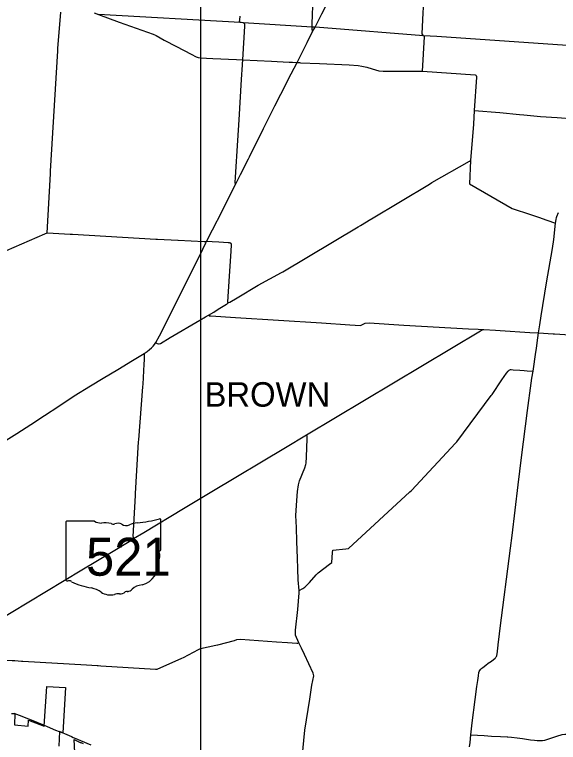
# Model space of a CAD drawing. Extents: x 1729596 to 1925846, y 659247 to 911751.
# Drawn here: x 1821771 to 1841732, y 833985 to 860705 of the extents above; entities that cross this region are included whole.
import ezdxf

# ---------------------------------------------------------------- set-up
doc = ezdxf.new("R2010")
doc.units = 0
for name, color, linetype in [('GM_X_Corporation', 7, 'Continuous'), ('GM_X_County_Road', 7, 'Continuous'), ('GM_X_State_Route', 7, 'Continuous'), ('GM_X_State_Shield', 7, 'Continuous'), ('GM_X_Township', 7, 'Continuous'), ('GM_X_Township_Road', 7, 'Continuous'), ('GM_X_Township_Text', 7, 'Continuous'), ('GM_X_US_Route', 7, 'Continuous'), ('SH_Data', 7, 'Continuous')]:
    doc.layers.add(name, color=color, linetype=linetype)

msp = doc.modelspace()

# ---------------------------------------------------------------- linework, layer by layer
at = {"layer": 'GM_X_Corporation'}
for points in [[(1821656, 835046), (1821781, 835050), (1821769, 834633), (1822268, 834587), (1822281, 834808), (1822854, 834577), (1822956, 836039), (1823645, 836005), (1823540, 834336), (1823415, 834383), (1823397, 833851)], [(1824058, 832202), (1823955, 834094), (1824182, 833983), (1824200, 833986), (1824290, 833942)]]:
    msp.add_lwpolyline(points, dxfattribs=at)
at = {"layer": 'GM_X_County_Road'}
for points in [[(1824699, 860768), (1824857, 860710), (1825612, 860430), (1826656, 860059), (1826853, 859982), (1826971, 859934), (1827258, 859768), (1827710, 859527), (1828254, 859247), (1828432, 859153), (1828513, 859123), (1828584, 859112), (1829052, 859088), (1829917, 859051), (1830145, 859048), (1831204, 858991), (1831412, 858982), (1831846, 858956), (1831978, 858953), (1832140, 858950)], [(1832140, 858950), (1832225, 858943), (1832265, 858939), (1832961, 858909), (1834057, 858860), (1834388, 858837), (1834514, 858807), (1834697, 858768), (1834897, 858714), (1835014, 858675), (1835136, 858637), (1835294, 858625), (1835692, 858625), (1836196, 858623), (1836448, 858626), (1836739, 858621)], [(1836739, 858621), (1838675, 858491), (1838704, 858476), (1838715, 858460)], [(1838715, 858460), (1838725, 858446), (1838731, 858409), (1838644, 857189), (1838612, 856680), (1838509, 855352), (1838468, 854485), (1840033, 853588), (1840704, 853369), (1840998, 853268), (1841304, 853162), (1841625, 853051)], [(1841006, 849018), (1841051, 849314), (1841101, 849645), (1841295, 850857), (1841512, 852119), (1841560, 852444), (1841625, 853051), (1841645, 853178), (1841666, 853257), (1841678, 853296), (1841734, 853436)], [(1827483, 848845), (1828569, 849486), (1828773, 849606), (1828890, 849668)], [(1828890, 849668), (1828890, 849668), (1828924, 849648), (1828977, 849643), (1829879, 849585), (1833037, 849389), (1834076, 849311), (1834469, 849288), (1834642, 849380), (1834781, 849392), (1836063, 849299), (1838431, 849174), (1838783, 849153), (1838998, 849141)], [(1838466, 833825), (1838487, 833985), (1838519, 834265), (1838567, 834705), (1838674, 835560), (1838743, 836040), (1838773, 836253), (1838796, 836429), (1838814, 836551), (1838826, 836590), (1838844, 836629), (1838867, 836664), (1838885, 836685), (1838954, 836740), (1839072, 836824), (1839157, 836890), (1839273, 836974), (1839413, 837081), (1839426, 837095), (1839438, 837110), (1839458, 837143), (1839466, 837161), (1839472, 837179), (1839477, 837198), (1839478, 837221), (1839510, 837440), (1839538, 837684), (1839547, 837760), (1839596, 838176), (1839967, 841111), (1840035, 841581), (1840259, 843439), (1840381, 844450), (1840596, 846166), (1840736, 847171), (1840762, 847354), (1840807, 847615), (1840906, 848311), (1840922, 848444), (1840955, 848656), (1841006, 849018)], [(1826954, 848664), (1826976, 848639), (1827002, 848628), (1827054, 848615), (1827084, 848617), (1827126, 848635), (1827483, 848845)], [(1824834, 836804), (1824939, 836797), (1826941, 836673), (1827000, 836670), (1827915, 837079), (1827969, 837103), (1828528, 837401), (1828591, 837434), (1829159, 837555), (1829234, 837570), (1829847, 837731), (1829932, 837765), (1830068, 837770), (1831380, 837679), (1831789, 837651), (1832132, 837627), (1832164, 837633), (1832207, 837647), (1832086, 837925), (1832077, 837968), (1832081, 838107), (1832167, 838864), (1832211, 839479), (1832217, 839559), (1832354, 839640), (1832420, 839679), (1832530, 839793), (1832596, 839862), (1832843, 840137), (1832910, 840211), (1833329, 840531), (1833411, 840594), (1833446, 840962), (1833453, 841041), (1833926, 841092), (1834029, 841103), (1836280, 843180), (1836334, 843229), (1837952, 844970), (1838003, 845024), (1839263, 846719), (1839296, 846763), (1839657, 847296), (1839829, 847544), (1839890, 847618), (1839921, 847646), (1839949, 847661), (1839978, 847670), (1839994, 847672), (1840065, 847668), (1840312, 847648), (1840471, 847640), (1840580, 847631), (1840807, 847615)], [(1820825, 837049), (1820913, 837042), (1821680, 836994), (1821777, 836987), (1822028, 836972), (1822074, 836969)], [(1822074, 836969), (1824417, 836829)], [(1824417, 836829), (1824803, 836806), (1824834, 836804), (1824834, 836804)]]:
    msp.add_lwpolyline(points, dxfattribs=at)
at = {"layer": 'GM_X_State_Route'}
for points in [[(1824240, 840319), (1825270, 840939), (1826096, 841440), (1826142, 841474), (1826514, 841694), (1827976, 842576), (1829017, 843200), (1831719, 844816), (1832490, 845282), (1838868, 849097), (1838914, 849121), (1838998, 849141), (1839418, 849116)], [(1839418, 849116), (1839597, 849106), (1840678, 849037), (1841006, 849018)], [(1841006, 849018), (1841537, 848985), (1841586, 848982)], [(1841586, 848982), (1842167, 848948), (1842431, 848928)], [(1820468, 838053), (1820655, 838166), (1821648, 838759), (1824240, 840319)]]:
    msp.add_lwpolyline(points, dxfattribs=at)
at = {"layer": 'GM_X_State_Shield'}
for p, q in [((1823657, 842070), (1823657, 839957)), ((1823657, 842070), (1823657, 839957)), ((1824710, 842107), (1823691, 842107)), ((1824710, 842107), (1823691, 842107)), ((1827137, 841053), (1827137, 842159)), ((1827137, 841053), (1827137, 842159)), ((1827137, 841054), (1827137, 841053)), ((1827137, 841054), (1827137, 841053))]:
    msp.add_line(p, q, dxfattribs=at)
for centre, major_axis, start_param, end_param in [((1823697, 842075), (40.3, 0), 1.712693, 3.28349), ((1823697, 842075), (40.3, 0), 1.712693, 3.28349), ((1824953, 842352), (391, 0), 4.042523, 4.731795), ((1824953, 842352), (391, 0), 4.042523, 4.731795), ((1825083, 840920), (1404, 0), 1.404758, 1.657858), ((1825083, 840920), (1404, 0), 1.404758, 1.657858), ((1825402, 842086), (113, 0), 3.836095, 5.185415), ((1825402, 842086), (113, 0), 3.836095, 5.185415), ((1825567, 841841), (235, 0), 0.950623, 2.079405), ((1825567, 841841), (235, 0), 0.950623, 2.079405), ((1825870, 842176), (282, 0), 4.081561, 5.145723), ((1825870, 842176), (282, 0), 4.081561, 5.145723), ((1826368, 841461), (743, 0), 1.699011, 2.107814), ((1826368, 841461), (743, 0), 1.699011, 2.107814), ((1825898, 844988), (3691, 0), 4.814394, 5.042369), ((1825898, 844988), (3691, 0), 4.814394, 5.042369), ((1827099, 842163), (38.7, 0), 6.141152, 7.989035), ((1827099, 842163), (38.7, 0), 6.141152, 7.989035), ((1827128, 840972), (60, 0), 1.883978, 3.671073), ((1827128, 840972), (60, 0), 1.883978, 3.671073), ((1826747, 840833), (360, 0), 5.934695, 6.695948), ((1826747, 840833), (360, 0), 5.934695, 6.695948), ((1827096, 841049), (41.5, 0), 5.05454, 6.418171), ((1827096, 841049), (41.5, 0), 5.05454, 6.418171), ((1827276, 840591), (262, 0), 2.387724, 3.262537), ((1827276, 840591), (262, 0), 2.387724, 3.262537), ((1826104, 840450), (923, 0), 5.101752, 6.440018), ((1826104, 840450), (923, 0), 5.101752, 6.440018), ((1823697, 839952), (40.7, 0), 3.00124, 4.508301), ((1823697, 839952), (40.7, 0), 3.00124, 4.508301), ((1823703, 840168), (310, 0), 4.665946, 4.897461), ((1823703, 840168), (310, 0), 4.665946, 4.897461), ((1823767, 839835), (112, 0), 0.519207, 1.627899), ((1823767, 839835), (112, 0), 0.519207, 1.627899), ((1825180, 841734), (2665, 0), 4.195997, 4.488961), ((1825180, 841734), (2665, 0), 4.195997, 4.488961), ((1824385, 839008), (834, 0), 0.823519, 1.323587), ((1824385, 839008), (834, 0), 0.823519, 1.323587), ((1825853, 839752), (298, 0), 4.937069, 5.64225), ((1825853, 839752), (298, 0), 4.937069, 5.64225), ((1826494, 839364), (506, 0), 1.647645, 2.488434), ((1826494, 839364), (506, 0), 1.647645, 2.488434), ((1825287, 839824), (529, 0), 4.026481, 4.996735), ((1825287, 839824), (529, 0), 4.026481, 4.996735), ((1825593, 839094), (435, 0), 1.495662, 1.94098), ((1825593, 839094), (435, 0), 1.495662, 1.94098), ((1825632, 839666), (282, 0), 4.691044, 5.507374), ((1825632, 839666), (282, 0), 4.691044, 5.507374), ((1825887, 839462), (79.4, 0), 1.147584, 2.315152), ((1825887, 839462), (79.4, 0), 1.147584, 2.315152)]:
    msp.add_ellipse(centre, major_axis=major_axis, ratio=0.8, start_param=start_param, end_param=end_param, dxfattribs=at)
at = {"layer": 'GM_X_Township'}
msp.add_lwpolyline([(1848864, 860810), (1848787, 859601), (1848752, 859146), (1848243, 859177), (1843111, 859493), (1837275, 859897), (1836785, 859928), (1833125, 860220), (1832799, 860239), (1832694, 860243), (1830166, 860402), (1830089, 860410), (1830057, 860416), (1824857, 860710)], dxfattribs=at)
at = {"layer": 'GM_X_Township_Road'}
for points in [[(1832712, 860086), (1832692, 860180), (1832694, 860243), (1832711, 860815), (1832717, 860894), (1832916, 864638), (1832920, 864735), (1833003, 866422), (1833008, 866525), (1833111, 868476), (1833115, 868570)], [(1836801, 859906), (1836785, 859928), (1836730, 860003), (1836772, 860771), (1836832, 861759), (1836900, 861806), (1837774, 861777), (1841815, 864609), (1841870, 865582)], [(1822973, 852697), (1823090, 854855), (1823095, 854950), (1823360, 859378), (1823364, 859462), (1823464, 860797)], [(1830145, 859048), (1830219, 860280), (1830222, 860351), (1830198, 860382), (1830166, 860402), (1830089, 860410), (1830057, 860416), (1830033, 860449), (1830040, 860509), (1830047, 860642)], [(1836739, 858621), (1836819, 859882), (1836801, 859906)], [(1829879, 854468), (1829867, 854539), (1829884, 854733), (1829968, 856079), (1830015, 856843), (1830104, 858325), (1830133, 858863), (1830135, 858890)], [(1830135, 858890), (1830145, 859048)], [(1838644, 857189), (1839578, 857114), (1840298, 857042)], [(1840298, 857042), (1840462, 857025), (1841078, 856968), (1841688, 856928), (1842311, 856878), (1843277, 856832), (1843501, 856817), (1844772, 856764), (1845200, 856735), (1845320, 856733)], [(1834871, 853208), (1837006, 854484), (1837090, 854534), (1838463, 855326), (1838509, 855352)], [(1829632, 850131), (1829670, 850148), (1829937, 850308), (1830715, 850775), (1831571, 851235), (1831618, 851263), (1834382, 852917), (1834467, 852967), (1834850, 853196), (1834871, 853208)], [(1821238, 851978), (1821378, 852020), (1821474, 852048), (1822880, 852657), (1822973, 852697), (1822981, 852696), (1823816, 852647), (1823896, 852643), (1826953, 852461), (1827020, 852457), (1827766, 852423)], [(1827766, 852423), (1827772, 852422), (1828724, 852374), (1828817, 852370)], [(1829609, 850120), (1829604, 850137), (1829602, 850154), (1829661, 851097), (1829717, 852021), (1829733, 852247), (1829733, 852268), (1829728, 852285), (1829722, 852293), (1829709, 852307), (1829695, 852315), (1829689, 852317), (1829659, 852321), (1829617, 852324), (1829269, 852344), (1829020, 852358), (1828817, 852370)], [(1828890, 849668), (1829079, 849784), (1829169, 849839), (1829310, 849931), (1829553, 850077), (1829575, 850092), (1829609, 850120), (1829632, 850131)], [(1826484, 847033), (1826485, 847041), (1826492, 847131), (1826529, 847868), (1826535, 848025), (1826539, 848226), (1826523, 848267)], [(1826142, 841474), (1826131, 841521), (1826129, 841545), (1826206, 843055), (1826209, 843120), (1826326, 845018), (1826330, 845093), (1826484, 847033)], [(1832217, 839559), (1832181, 839958), (1832166, 840360), (1832150, 840747), (1832131, 841365), (1832119, 841876), (1832100, 842311), (1832130, 842865), (1832154, 843199), (1832190, 843436), (1832231, 843590), (1832429, 844063), (1832467, 844186), (1832471, 844240), (1832481, 844468), (1832506, 845131), (1832505, 845224), (1832490, 845282)], [(1832327, 833414), (1832426, 834435), (1832607, 835575), (1832687, 836093), (1832759, 836431), (1832731, 836526), (1832414, 837215), (1832308, 837446), (1832207, 837647)], [(1838519, 834265), (1839003, 834239), (1839280, 834220), (1839610, 834202), (1839845, 834186), (1839872, 834185)], [(1839872, 834185), (1840004, 834176), (1840213, 834155), (1840314, 834142), (1840419, 834128), (1840709, 834086), (1840854, 834066), (1840955, 834057), (1841058, 834052), (1841152, 834058), (1841236, 834072), (1841340, 834101), (1841488, 834149), (1841639, 834205), (1841751, 834242), (1841801, 834256), (1841870, 834271), (1841962, 834284), (1842018, 834287), (1842093, 834287), (1842280, 834278)]]:
    msp.add_lwpolyline(points, dxfattribs=at)
at = {"layer": 'GM_X_US_Route'}
for points in [[(1832814, 860270), (1833045, 860728), (1833707, 862039), (1833995, 862623), (1834269, 863162), (1835215, 865051), (1835681, 865996), (1836078, 866774), (1836442, 867502), (1837331, 869279), (1837642, 869882), (1838022, 870648), (1838475, 871555), (1838873, 872351), (1839135, 872864), (1840316, 875226), (1840905, 876404)], [(1830354, 855412), (1830390, 855482), (1830910, 856524), (1831328, 857349), (1831761, 858212), (1831835, 858364), (1831922, 858529), (1832140, 858950), (1832178, 859024), (1832261, 859187), (1832516, 859678), (1832712, 860086), (1832799, 860239), (1832814, 860270)], [(1829567, 853847), (1829623, 853958), (1829773, 854260), (1829879, 854468), (1830065, 854836), (1830354, 855412)], [(1828794, 852323), (1828817, 852370), (1829042, 852803), (1829388, 853493), (1829567, 853847)], [(1826523, 848267), (1826643, 848340), (1826727, 848406), (1826792, 848465), (1826862, 848537), (1826902, 848592), (1826954, 848664), (1827089, 848914), (1827795, 850319), (1828063, 850849), (1828568, 851857), (1828794, 852323)], [(1815985, 842997), (1816140, 843045), (1816516, 843159), (1818004, 843604), (1819466, 844036), (1819970, 844186), (1820078, 844226), (1820154, 844261), (1820230, 844302), (1820378, 844395), (1820678, 844582), (1820789, 844650), (1821371, 845021), (1821564, 845146), (1821850, 845326), (1822366, 845660), (1822875, 845990), (1823392, 846332), (1823964, 846703), (1824557, 847070), (1825025, 847354), (1825562, 847681), (1826103, 848010), (1826523, 848267)], [(1821742, 835058), (1821837, 835019), (1821938, 834981)], [(1821938, 834981), (1822282, 834851), (1822381, 834811)], [(1822381, 834811), (1822857, 834621), (1822968, 834573)], [(1822968, 834573), (1823279, 834440), (1823404, 834391), (1823504, 834351)], [(1823504, 834351), (1823539, 834337), (1823602, 834310)], [(1823602, 834310), (1823863, 834198), (1823927, 834172), (1823961, 834158), (1824572, 833896)]]:
    msp.add_lwpolyline(points, dxfattribs=at)
at = {"layer": 'SH_Data'}
msp.add_line((1828599, 890928), (1828599, 814428), dxfattribs=at)

# ---------------------------------------------------------------- texts
at = {"layer": 'GM_X_State_Shield'}
msp.add_text('521', height=1392.2, dxfattribs=at).set_placement((1824394, 840106))
msp.add_text('521', height=1392.2, dxfattribs=at).set_placement((1824394, 840106))
at = {"layer": 'GM_X_Township_Text'}
msp.add_text('BROWN', height=900, rotation=0, dxfattribs=at).set_placement((1828743, 846310))

doc.saveas('drawing.dxf')
